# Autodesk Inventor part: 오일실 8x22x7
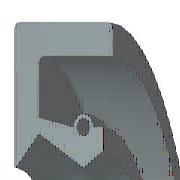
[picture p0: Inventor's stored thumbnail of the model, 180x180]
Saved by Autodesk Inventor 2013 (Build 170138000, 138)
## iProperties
IsCustomPart: 1
Created: 2009-02
Part Number: 오일실 8x22x7
Material: 고무
Description: 오일-실
Document SubType Name: Modeling
Standard: KS B 2804
Designer: 한국산업디자인학원
Standards Organization: KS
Language: ko-KR
Size Designation: D - 8 22 7
Categories: <MemberInstance><Categories><Category DisplayName="샤프트 부품" InternalName="7f7aeb1f-a693-4053-b835-cee3144e0d98" Mnemonic="SHFT"><Category DisplayName="실링" Intern
Density: 0.93 g/cm^3
Author: 한국산업디자인학원
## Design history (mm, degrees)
revolve "본체" stored, may be unused: angle "d17" = 90 deg
revolve "스프링1" stored, may be unused: angle "d18" = 90 deg
body "Solid1"
sketch "스케치1"
  geometry: L1 (0, 11)-(7, 11); L2 (7, 9.25)-(1.75, 9.25); L3 (1.75, 5.75)-(4.9, 4); L4 (4.9, 4)-(0, 4); L5 (0, 0)-(9.586, 0) reference; L6 (4.9, 4)-(6.3, 4.875); L7 (0, 18)-(0, -3) reference; L8 (-1.941, 0)-(11.507, 0) reference; L9 (4.2, 6.1)-(1.75, 6.59); L10 (1.75, 6.59)-(1.75, 9.25); L11 (0, 11)-(0, 4.088); L12 (4.9, 4)-(0, 4); L13 (1.75, 5.75)-(0.152, 4.028); L14 (7, 11)-(7, 9.25); L15 (5.6, 6.1)-(6.3, 6.1); L16 (6.3, 6.1)-(6.3, 4.875); C1 r 0.455 at (4.9, 6.1); A1 r 0.7 centre (4.9, 6.1) between (5.6, 6.1) and (4.2, 6.1); A2 r 0.088 centre (0.088, 4.088) between (0, 4.088) and (0.152, 4.028); 1 further point
  constraints: 28 end point, 5 horizontal alignment, 5 point on line, 4 point on circle, 4 vertical alignment, 3 centre point, 3 tangent, 2 collinear, 2 horizontal, 2 perpendicular, 1 coincident, 1 parallel
  dimensions: "d0" = 22 diameter of L1 L5 (= SD2); "d1" = 1.75 distance of L1.end L2.start (= SD); "d2" = 0.91 diameter of C1 (= SPDI); "d3" = 1.4 diameter of A1 (= SPDA); "d4" = 8 diameter of L3.end L5 (= NND); "d5" = 11.5 diameter of L3.start L5 (= TKDM); "d7" = 13.18 diameter of L9.end L5 (= TKDM + 0.24 x SWDT); "d8" = 1.75 distance between parallel lines of L11 L10 (= SD); "d9" = 4.9 distance from line of L11 C1.centre (= SPDST); "d10" = 12.2 diameter of C1.centre L5 (= HLDM); "d11" = 0.0875 radius of A2 (= 0.25 x LAB); "d12" = 6.3 distance between parallel lines of L11 L16 (= SDI); "d13" = 9.75 diameter of L6.end L5 (= ABDM); "d14" = 7 distance from line of L11 L1.end (= SWDT)
fillet "모깎기1" dims "d6" = 0.3 (= RR)
other parameters: "SD2" = 22 [user parameter; used in 1 equation term], "SWDT" = 7 [user parameter; used in 2 equation terms], "RR" = 0.3 [user parameter; used in 1 equation term], "SD" = 1.75 [user parameter; used in 2 equation terms], "NND" = 8 [user parameter; used in 1 equation term], "SPDA" = 1.4 [user parameter; used in 1 equation term], "SPDI" = 0.91 [user parameter; used in 1 equation term], "TKDM" = 11.5 [user parameter; used in 2 equation terms], "HLDM" = 12.2 [user parameter; used in 1 equation term], "ABDM" = 9.75 [user parameter; used in 1 equation term], "SDI" = 6.3 [user parameter; used in 1 equation term], "SPDST" = 4.9 [user parameter; used in 1 equation term], "LAB" = 0.35 [user parameter; used in 1 equation term], "d15" = 0, "d16" = 0, "d19" = 0
